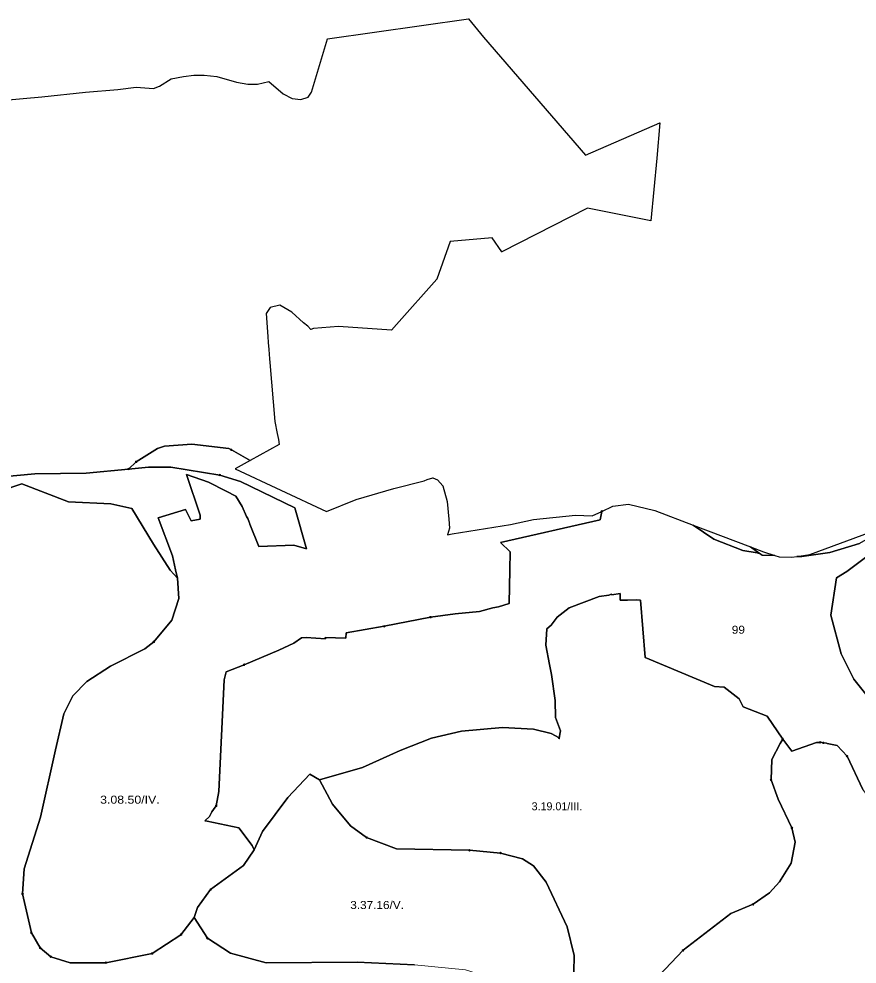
# Model space of a CAD drawing. Extents: x -650455 to -642254, y -1075222 to -1066610.
# Drawn here: x -644814 to -643766, y -1069625 to -1068444 of the extents above; entities that cross this region are included whole.
import ezdxf
from ezdxf.enums import TextEntityAlignment as Align

# ---------------------------------------------------------------- set-up
doc = ezdxf.new("R2010")
doc.units = 0
doc.header["$LTSCALE"] = 4
doc.header["$PDMODE"] = 32
doc.header["$PDSIZE"] = 2
for name, color, linetype, lineweight in [('1', 7, 'Continuous', 25), ('11', 7, 'Continuous', 13), ('13', 7, 'Continuous', 13), ('14', 7, 'Continuous', 13), ('15', 7, 'Continuous', 13)]:
    doc.layers.add(name, color=color, linetype=linetype, lineweight=lineweight)
doc.layers.add('2', color=7, linetype='Continuous')

msp = doc.modelspace()

# ---------------------------------------------------------------- linework, layer by layer
at = {"layer": '1'}
for points in [[(-644865.029, -1068548.219), (-644785.549, -1068541.387), (-644730.78, -1068535.476), (-644690.424, -1068532.018), (-644667.364, -1068529.135), (-644646.033, -1068530.865), (-644638.25, -1068527.839), (-644623.837, -1068518.903), (-644608.271, -1068515.731), (-644595.299, -1068514.291), (-644582.328, -1068514.291), (-644566.762, -1068515.875), (-644542.26, -1068523.081), (-644527.847, -1068525.533), (-644515.877, -1068525.233), (-644501.596, -1068522.127), (-644483.899, -1068537.657), (-644472.722, -1068543.249), (-644461.856, -1068544.49), (-644452.542, -1068541.695), (-644448.506, -1068535.484), (-644428.326, -1068468.706), (-644252.29, -1068443.858), (-644233.352, -1068466.531)], [(-644233.352, -1068466.531), (-644105.749, -1068614.065), (-644012.919, -1068573.686), (-644016.645, -1068617.791), (-644024.406, -1068696.372), (-644103.575, -1068680.531), (-644210.376, -1068734.886), (-644222.484, -1068717.492), (-644275.263, -1068722.151), (-644291.718, -1068769.051), (-644342.212, -1068825.639), (-644348.534, -1068832.723), (-644414.741, -1068828.435), (-644445.788, -1068830.92), (-644449.35, -1068832.01), (-644452.802, -1068828.111), (-644458.176, -1068823.819), (-644472.804, -1068810.471), (-644488.017, -1068801.775), (-644500.125, -1068804.57), (-644505.092, -1068812.026), (-644502.911, -1068840.68), (-644502.338, -1068848.206), (-644501.654, -1068857.202), (-644500.772, -1068868.778), (-644500.435, -1068873.213), (-644494.115, -1068947.011), (-644491.207, -1068961.854), (-644489.705, -1068969.518), (-644488.773, -1068975.73), (-644525.181, -1068995.897), (-644548.5, -1068982.501), (-644551.5, -1068981.001), (-644598, -1068975.5), (-644632, -1068978.001), (-644641, -1068981.001), (-644667.5, -1068997.501), (-644677, -1069006.501), (-644730, -1069011.5), (-644794, -1069012.5)], [(-644640, -1069067.501), (-644606, -1069057), (-644598.81, -1069071.02), (-644587.5, -1069069), (-644587.5, -1069064), (-644604.5, -1069013.501), (-644577, -1069023.001), (-644555, -1069034.001), (-644543, -1069040.5), (-644535.13, -1069053.181), (-644529.464, -1069065.769), (-644528, -1069068.5), (-644526.232, -1069072.948), (-644525.83, -1069073.84), (-644525.345, -1069075.177), (-644514.093, -1069103.478), (-644470.37, -1069101.551), (-644454.63, -1069106.281), (-644469.28, -1069054.8), (-644537, -1069022.001), (-644563, -1069014.001), (-644624, -1069004), (-644652, -1069004), (-644677, -1069006.501), (-644667.5, -1068997.501), (-644641, -1068981.001), (-644632, -1068978.001), (-644598, -1068975.5), (-644551.5, -1068981.001), (-644548.5, -1068982.501), (-644525.181, -1068995.897)], [(-644839.5, -1069016.5), (-644794, -1069012.5), (-644730, -1069011.5), (-644677, -1069006.501), (-644652, -1069004), (-644624, -1069004), (-644563, -1069014.001), (-644537, -1069022.001), (-644469.28, -1069054.8), (-644454.63, -1069106.281), (-644470.37, -1069101.551), (-644514.093, -1069103.478), (-644525.345, -1069075.177), (-644525.83, -1069073.84), (-644526.232, -1069072.948), (-644528, -1069068.5), (-644529.464, -1069065.769), (-644535.13, -1069053.181), (-644543, -1069040.5)], [(-644525.181, -1068995.897), (-644543.726, -1069006.168), (-644429.474, -1069059.592), (-644392.528, -1069044.683), (-644345.647, -1069030.706), (-644307.77, -1069021.078), (-644303.667, -1069019.725), (-644296.6, -1069017.395), (-644290.701, -1069019.88), (-644284.181, -1069027.644), (-644278.903, -1069047.211), (-644276.818, -1069069.004), (-644275.887, -1069080.185), (-644278.515, -1069088.547), (-644272.734, -1069087.604), (-644199.819, -1069075.69), (-644170.945, -1069069.479), (-644118.477, -1069064.198), (-644097.468, -1069064.949), (-644085.664, -1069059.379), (-644087.5, -1069070.001), (-644212, -1069098.501), (-644200, -1069110), (-644200.5, -1069132.5), (-644201.5, -1069174.5), (-644214.53, -1069178.601), (-644221.69, -1069179.9), (-644238.23, -1069184.641), (-644268.7, -1069187.421), (-644299.717, -1069191.596), (-644357.5, -1069203), (-644405, -1069211), (-644405.5, -1069218), (-644431.362, -1069216.923), (-644430.91, -1069218.821), (-644454.87, -1069217.05), (-644460.97, -1069217.61), (-644470.64, -1069224.001), (-644489.27, -1069233.04), (-644532.71, -1069251.121)], [(-644794, -1069012.5), (-644839.5, -1069016.5)], [(-644543, -1069040.5), (-644555, -1069034.001), (-644577, -1069023.001), (-644604.5, -1069013.501), (-644587.5, -1069064), (-644587.5, -1069069), (-644598.81, -1069071.02), (-644606, -1069057), (-644640, -1069067.501), (-644622, -1069115.001), (-644618.28, -1069132.421), (-644616, -1069143.001)], [(-644616, -1069143.001), (-644625, -1069133), (-644646, -1069100.5), (-644673, -1069056), (-644699, -1069050.001), (-644752, -1069047.5), (-644810.5, -1069025), (-644836.38, -1069033.691)], [(-644836.38, -1069033.691), (-644810.5, -1069025), (-644752, -1069047.5), (-644699, -1069050.001)], [(-644699, -1069050.001), (-644673, -1069056), (-644646, -1069100.5), (-644625, -1069133), (-644616, -1069143.001)], [(-644357.5, -1069203), (-644299.717, -1069191.596), (-644268.7, -1069187.421), (-644238.23, -1069184.641), (-644221.69, -1069179.9), (-644214.53, -1069178.601), (-644201.5, -1069174.5), (-644200.5, -1069132.5), (-644200, -1069110), (-644212, -1069098.501), (-644087.5, -1069070.001), (-644085.664, -1069059.379), (-644071.881, -1069052.874), (-644052.196, -1069050.206), (-644019.287, -1069058.281), (-643971.567, -1069076.484)], [(-644532.71, -1069251.121), (-644555, -1069260), (-644557.5, -1069270.001), (-644564, -1069409.5), (-644567.5, -1069427.501), (-644571, -1069432.001), (-644572.97, -1069435.121), (-644575.93, -1069440.66), (-644581.87, -1069446.281), (-644578.92, -1069446.801), (-644539, -1069454.881), (-644522.5, -1069477), (-644520, -1069482.5), (-644533.5, -1069502), (-644574.5, -1069532.001), (-644591, -1069554.5), (-644595, -1069567), (-644611.5, -1069588.501), (-644647.5, -1069612), (-644705.5, -1069623.5), (-644750, -1069623.5), (-644774, -1069616), (-644787.5, -1069605.001), (-644798.5, -1069586), (-644809.5, -1069537.5), (-644807.5, -1069506), (-644787, -1069441.5), (-644768.5, -1069357.501), (-644758, -1069312.5), (-644746.5, -1069290.001), (-644729, -1069272), (-644699.5, -1069253.001), (-644656.5, -1069231), (-644645.5, -1069222.5), (-644623, -1069195.501), (-644614, -1069168.501), (-644616, -1069143.001), (-644618.28, -1069132.421), (-644622, -1069115.001), (-644640, -1069067.501)], [(-643971.567, -1069076.484), (-643945.5, -1069094), (-643909.5, -1069108.5), (-643891.564, -1069111.125), (-643891.55, -1069111.13), (-643890.13, -1069111.65), (-643888.83, -1069111.611), (-643888.824, -1069111.61), (-643885, -1069114), (-643869.425, -1069114.63), (-643864.053, -1069116.363), (-643848.219, -1069116.674), (-643842.005, -1069115.738), (-643835.5, -1069116.001), (-643800.5, -1069111.001), (-643763.5, -1069099.501)], [(-643747.75, -1069110.71), (-643779.31, -1069134.631), (-643792.04, -1069142.271), (-643799.5, -1069189.001), (-643786.5, -1069237.501), (-643770.5, -1069269.001), (-643744, -1069302.5)], [(-643744, -1069302.5), (-643770.5, -1069269.001), (-643786.5, -1069237.501), (-643799.5, -1069189.001), (-643792.04, -1069142.271), (-643779.31, -1069134.631), (-643747.75, -1069110.71)], [(-644616, -1069143.001), (-644614, -1069168.501), (-644623, -1069195.501), (-644645.5, -1069222.5), (-644656.5, -1069231), (-644699.5, -1069253.001), (-644729, -1069272), (-644746.5, -1069290.001), (-644758, -1069312.5), (-644768.5, -1069357.501), (-644787, -1069441.5), (-644807.5, -1069506), (-644809.5, -1069537.5), (-644798.5, -1069586), (-644787.5, -1069605.001), (-644774, -1069616), (-644750, -1069623.5), (-644705.5, -1069623.5), (-644647.5, -1069612), (-644611.5, -1069588.501), (-644595, -1069567), (-644578.5, -1069593.001), (-644549.5, -1069611.5), (-644505, -1069623.5), (-644391.5, -1069623), (-644319.5, -1069626.001)], [(-644209.5, -1069329.501), (-644171, -1069331.5), (-644149, -1069337.001), (-644139, -1069342.501), (-644137, -1069333.501), (-644143.54, -1069317.051), (-644144.05, -1069295.67), (-644148.22, -1069263.22), (-644151.11, -1069250.7), (-644155.37, -1069226.72), (-644154.36, -1069206.06), (-644148.931, -1069201.554), (-644141.5, -1069191.501), (-644126.5, -1069180.001), (-644089, -1069166), (-644076.643, -1069164.135), (-644073.35, -1069162.84), (-644073.229, -1069163.62), (-644062.5, -1069162), (-644062.5, -1069170.5), (-644053.451, -1069170.5), (-644042.37, -1069169.77), (-644037, -1069170.5), (-644031.5, -1069242), (-643944.89, -1069278.321), (-643932.5, -1069279), (-643914, -1069293.501), (-643909, -1069303.5), (-643879, -1069315.5), (-643859.5, -1069344)], [(-643759.5, -1069407.001), (-643779, -1069365.501), (-643791.5, -1069352), (-643803.851, -1069349.648), (-643804.83, -1069348.991), (-643808.723, -1069348.72), (-643812.5, -1069348), (-643813.705, -1069348.374), (-643817.06, -1069348.14), (-643848, -1069359.001), (-643859.5, -1069344), (-643879, -1069315.5), (-643909, -1069303.5), (-643914, -1069293.501), (-643932.5, -1069279), (-643944.89, -1069278.321), (-644031.5, -1069242), (-644037, -1069170.5), (-644042.37, -1069169.77), (-644053.451, -1069170.5), (-644062.5, -1069170.5), (-644062.5, -1069162), (-644073.229, -1069163.62), (-644073.35, -1069162.84), (-644076.643, -1069164.135), (-644089, -1069166), (-644126.5, -1069180.001), (-644141.5, -1069191.501), (-644148.931, -1069201.554), (-644154.36, -1069206.06), (-644155.37, -1069226.72), (-644151.11, -1069250.7)], [(-644151.11, -1069250.7), (-644148.22, -1069263.22), (-644144.05, -1069295.67), (-644143.54, -1069317.051), (-644137, -1069333.501), (-644139, -1069342.501), (-644149, -1069337.001), (-644171, -1069331.5), (-644209.5, -1069329.501), (-644261, -1069334.001), (-644298.5, -1069343), (-644337.6, -1069358.4), (-644350.5, -1069364), (-644384.5, -1069379.5), (-644438.5, -1069395.001), (-644450.5, -1069388), (-644478, -1069417), (-644509.5, -1069459.501), (-644520, -1069482.5), (-644522.5, -1069477), (-644539, -1069454.881), (-644578.92, -1069446.801), (-644581.87, -1069446.281), (-644575.93, -1069440.66), (-644572.97, -1069435.121), (-644571, -1069432.001), (-644567.5, -1069427.501), (-644564, -1069409.5), (-644557.5, -1069270.001), (-644555, -1069260), (-644532.71, -1069251.121), (-644489.27, -1069233.04), (-644470.64, -1069224.001), (-644460.97, -1069217.61), (-644454.87, -1069217.05), (-644430.91, -1069218.821), (-644431.362, -1069216.923), (-644405.5, -1069218), (-644405, -1069211), (-644357.5, -1069203)], [(-644121, -1069656), (-644120, -1069614.5), (-644129, -1069578.5), (-644155, -1069523), (-644171, -1069502.5), (-644184.5, -1069493.5), (-644212, -1069486.5), (-644251, -1069483.001), (-644342, -1069481), (-644379.5, -1069467.001), (-644399.5, -1069452.5), (-644422, -1069425.5), (-644438.5, -1069395.001), (-644384.5, -1069379.5), (-644350.5, -1069364), (-644337.6, -1069358.4), (-644298.5, -1069343), (-644261, -1069334.001), (-644209.5, -1069329.501)], [(-644014, -1069639.5), (-643984, -1069608), (-643924.5, -1069562), (-643896.5, -1069550.5), (-643876, -1069536.001), (-643863.5, -1069522.5), (-643849, -1069499.001), (-643844, -1069473), (-643848, -1069455.001), (-643865, -1069419.001), (-643874, -1069395.001), (-643873, -1069369.501), (-643862.5, -1069349.501), (-643859.5, -1069344), (-643848, -1069359.001), (-643817.06, -1069348.14)], [(-643859.5, -1069344), (-643862.5, -1069349.501), (-643873, -1069369.501), (-643874, -1069395.001), (-643865, -1069419.001), (-643848, -1069455.001), (-643844, -1069473), (-643849, -1069499.001), (-643863.5, -1069522.5), (-643876, -1069536.001), (-643896.5, -1069550.5), (-643924.5, -1069562), (-643984, -1069608), (-644014, -1069639.5)], [(-643817.06, -1069348.14), (-643813.705, -1069348.374), (-643812.5, -1069348), (-643808.723, -1069348.72), (-643804.83, -1069348.991), (-643803.851, -1069349.648), (-643791.5, -1069352), (-643779, -1069365.501), (-643759.5, -1069407.001)], [(-644319.5, -1069626.001), (-644391.5, -1069623), (-644505, -1069623.5), (-644549.5, -1069611.5), (-644578.5, -1069593.001), (-644595, -1069567), (-644591, -1069554.5), (-644574.5, -1069532.001), (-644533.5, -1069502), (-644520, -1069482.5), (-644509.5, -1069459.501), (-644478, -1069417), (-644450.5, -1069388), (-644438.5, -1069395.001), (-644422, -1069425.5), (-644399.5, -1069452.5), (-644379.5, -1069467.001), (-644342, -1069481), (-644251, -1069483.001), (-644212, -1069486.5), (-644184.5, -1069493.5), (-644171, -1069502.5), (-644155, -1069523), (-644129, -1069578.5), (-644120, -1069614.5), (-644121, -1069656)]]:
    msp.add_lwpolyline(points, dxfattribs=at)
for points in [[(-643888.83, -1069111.611), (-643890.13, -1069111.65), (-643891.55, -1069111.13), (-643891.564, -1069111.125), (-643909.5, -1069108.5), (-643945.5, -1069094), (-643971.567, -1069076.484), (-643899.857, -1069103.837), (-643889, -1069111.501), (-643888.836, -1069111.606)], [(-643800.5, -1069111.001), (-643835.5, -1069116.001), (-643842.005, -1069115.738), (-643825.555, -1069113.258), (-643740.798, -1069082.197), (-643738.043, -1069084.954), (-643763.5, -1069099.501)], [(-643883.302, -1069110.152), (-643869.425, -1069114.63), (-643885, -1069114), (-643888.824, -1069111.61), (-643888.83, -1069111.611), (-643888.836, -1069111.606), (-643889, -1069111.501), (-643899.857, -1069103.837)]]:
    msp.add_lwpolyline(points, close=True, dxfattribs=at)
at = {"layer": '11'}
msp.add_line((-643808.723, -1069348.72), (-643812.5, -1069348), dxfattribs=at)
for points in [[(-644667.5, -1068997.501), (-644641, -1068981.001), (-644632, -1068978.001), (-644598, -1068975.5), (-644551.5, -1068981.001), (-644548.5, -1068982.501), (-644525.181, -1068995.897), (-644488.773, -1068975.73), (-644489.705, -1068969.518), (-644491.207, -1068961.854), (-644494.115, -1068947.011), (-644500.435, -1068873.213), (-644500.772, -1068868.778), (-644501.654, -1068857.202), (-644502.338, -1068848.206), (-644502.911, -1068840.68), (-644505.092, -1068812.026), (-644500.125, -1068804.57), (-644488.017, -1068801.775), (-644472.804, -1068810.471), (-644458.176, -1068823.819), (-644452.802, -1068828.111), (-644449.35, -1068832.01), (-644445.788, -1068830.92), (-644414.741, -1068828.435), (-644348.534, -1068832.723), (-644342.212, -1068825.639), (-644291.718, -1068769.051), (-644275.263, -1068722.151), (-644222.484, -1068717.492), (-644210.376, -1068734.886), (-644103.575, -1068680.531), (-644024.406, -1068696.372), (-644016.645, -1068617.791), (-644012.919, -1068573.686), (-644105.749, -1068614.065), (-644233.352, -1068466.531), (-644252.29, -1068443.858), (-644428.326, -1068468.706), (-644448.506, -1068535.484)], [(-644448.506, -1068535.484), (-644452.542, -1068541.695), (-644461.856, -1068544.49), (-644472.722, -1068543.249), (-644483.899, -1068537.657), (-644501.596, -1068522.127), (-644515.877, -1068525.233), (-644527.847, -1068525.533), (-644542.26, -1068523.081), (-644566.762, -1068515.875), (-644582.328, -1068514.291), (-644595.299, -1068514.291), (-644608.271, -1068515.731), (-644623.837, -1068518.903), (-644638.25, -1068527.839), (-644646.033, -1068530.865), (-644667.364, -1068529.135), (-644690.424, -1068532.018), (-644730.78, -1068535.476), (-644785.549, -1068541.387), (-644865.029, -1068548.219)], [(-644884.5, -1069007), (-644872.563, -1069007.374), (-644875.563, -1068993.501), (-644867.701, -1068989.497), (-644855.56, -1068983.38), (-644851.16, -1069004.211), (-644851.147, -1069004.26), (-644850.813, -1069004.126), (-644849.51, -1069009.955), (-644839.5, -1069016.5), (-644794, -1069012.5), (-644730, -1069011.5), (-644677, -1069006.501), (-644667.5, -1068997.501)], [(-644809.5, -1069537.5), (-644807.5, -1069506), (-644787, -1069441.5), (-644768.5, -1069357.501), (-644758, -1069312.5), (-644746.5, -1069290.001), (-644729, -1069272), (-644699.5, -1069253.001), (-644656.5, -1069231), (-644645.5, -1069222.5), (-644623, -1069195.501), (-644614, -1069168.501), (-644616, -1069143.001), (-644625, -1069133), (-644646, -1069100.5), (-644673, -1069056), (-644699, -1069050.001), (-644752, -1069047.5), (-644810.5, -1069025), (-644836.38, -1069033.691)], [(-643859.5, -1069344), (-643862.5, -1069349.501), (-643873, -1069369.501), (-643874, -1069395.001)], [(-643812.5, -1069348), (-643813.705, -1069348.374), (-643817.06, -1069348.14), (-643848, -1069359.001), (-643859.5, -1069344)], [(-643779, -1069365.501), (-643791.5, -1069352), (-643803.851, -1069349.648), (-643804.83, -1069348.991), (-643808.723, -1069348.72)], [(-643727.662, -1069449.608), (-643759.5, -1069407.001), (-643779, -1069365.501)], [(-643874, -1069395.001), (-643865, -1069419.001), (-643848, -1069455.001), (-643844, -1069473), (-643849, -1069499.001), (-643863.5, -1069522.5), (-643876, -1069536.001), (-643896.5, -1069550.5), (-643924.5, -1069562), (-643984, -1069608)], [(-644787.5, -1069605.001), (-644798.5, -1069586), (-644809.5, -1069537.5)], [(-644578.5, -1069593.001), (-644595, -1069567), (-644611.5, -1069588.501)], [(-644611.5, -1069588.501), (-644647.5, -1069612), (-644705.5, -1069623.5)], [(-644217.5, -1069644.5), (-644256, -1069632.5), (-644319.5, -1069626.001), (-644391.5, -1069623), (-644505, -1069623.5), (-644549.5, -1069611.5), (-644578.5, -1069593.001)], [(-644705.5, -1069623.5), (-644750, -1069623.5), (-644774, -1069616), (-644787.5, -1069605.001)], [(-643984, -1069608), (-644014, -1069639.5), (-644062, -1069701), (-644056, -1069698.501), (-644086, -1069751.501), (-644087.496, -1069755.989), (-643999.727, -1069751.999), (-643995.5, -1069739.501)]]:
    msp.add_lwpolyline(points, dxfattribs=at)
for p in [(-644667.5, -1068997.501), (-643859.5, -1069344), (-643812.5, -1069348), (-643808.723, -1069348.72), (-643779, -1069365.501), (-643874, -1069395.001), (-644809.5, -1069537.5), (-644611.5, -1069588.501), (-644578.5, -1069593.001), (-644787.5, -1069605.001), (-643984, -1069608), (-644705.5, -1069623.5)]:
    msp.add_point(p, dxfattribs=at)
at = {"layer": '13'}
msp.add_line((-644251, -1069483.001), (-644212, -1069486.5), dxfattribs=at)
for points in [[(-643848, -1069455.001), (-643865, -1069419.001), (-643874, -1069395.001), (-643873, -1069369.501), (-643862.5, -1069349.501), (-643859.5, -1069344), (-643879, -1069315.5), (-643909, -1069303.5), (-643914, -1069293.501), (-643932.5, -1069279), (-643944.89, -1069278.321), (-644031.5, -1069242), (-644037, -1069170.5), (-644042.37, -1069169.77), (-644053.451, -1069170.5), (-644062.5, -1069170.5), (-644062.5, -1069162), (-644073.229, -1069163.62), (-644073.35, -1069162.84), (-644076.643, -1069164.135), (-644089, -1069166), (-644126.5, -1069180.001), (-644141.5, -1069191.501), (-644148.931, -1069201.554), (-644154.36, -1069206.06), (-644155.37, -1069226.72), (-644151.11, -1069250.7), (-644148.22, -1069263.22), (-644144.05, -1069295.67), (-644143.54, -1069317.051), (-644137, -1069333.501), (-644139, -1069342.501)], [(-644139, -1069342.501), (-644149, -1069337.001), (-644171, -1069331.5), (-644209.5, -1069329.501), (-644261, -1069334.001), (-644298.5, -1069343), (-644337.6, -1069358.4), (-644350.5, -1069364), (-644384.5, -1069379.5), (-644438.5, -1069395.001), (-644422, -1069425.5), (-644399.5, -1069452.5), (-644379.5, -1069467.001)], [(-643896.5, -1069550.5), (-643876, -1069536.001), (-643863.5, -1069522.5), (-643849, -1069499.001), (-643844, -1069473), (-643848, -1069455.001)], [(-644379.5, -1069467.001), (-644342, -1069481), (-644251, -1069483.001)], [(-644212, -1069486.5), (-644184.5, -1069493.5), (-644171, -1069502.5), (-644155, -1069523), (-644129, -1069578.5), (-644120, -1069614.5), (-644121, -1069656), (-644126, -1069675.5), (-644140, -1069691.001), (-644156, -1069689), (-644140, -1069712), (-644126, -1069716.5), (-644097.5, -1069715.001), (-644062, -1069701), (-644014, -1069639.5), (-643984, -1069608)], [(-643984, -1069608), (-643924.5, -1069562), (-643896.5, -1069550.5)]]:
    msp.add_lwpolyline(points, dxfattribs=at)
for p in [(-644139, -1069342.501), (-643848, -1069455.001), (-644379.5, -1069467.001), (-644251, -1069483.001), (-644212, -1069486.5), (-643896.5, -1069550.5), (-643984, -1069608)]:
    msp.add_point(p, dxfattribs=at)
at = {"layer": '14'}
for p, q in [((-644357.5, -1069203), (-644299.717, -1069191.596)), ((-644798.5, -1069586), (-644787.5, -1069605.001)), ((-644787.5, -1069605.001), (-644774, -1069616))]:
    msp.add_line(p, q, dxfattribs=at)
for points in [[(-644548.5, -1068982.501), (-644551.5, -1068981.001), (-644598, -1068975.5), (-644632, -1068978.001), (-644641, -1068981.001), (-644667.5, -1068997.501), (-644677, -1069006.501)], [(-644085.664, -1069059.379), (-644097.468, -1069064.949), (-644118.477, -1069064.198), (-644170.945, -1069069.479), (-644199.819, -1069075.69), (-644272.734, -1069087.604), (-644278.515, -1069088.547), (-644275.887, -1069080.185), (-644276.818, -1069069.004), (-644278.903, -1069047.211), (-644284.181, -1069027.644), (-644290.701, -1069019.88), (-644296.6, -1069017.395), (-644303.667, -1069019.725), (-644307.77, -1069021.078), (-644345.647, -1069030.706), (-644392.528, -1069044.683), (-644429.474, -1069059.592), (-644543.726, -1069006.168), (-644525.181, -1068995.897), (-644548.5, -1068982.501)], [(-644677, -1069006.501), (-644652, -1069004), (-644624, -1069004), (-644563, -1069014.001)], [(-644563, -1069014.001), (-644537, -1069022.001), (-644469.28, -1069054.8), (-644454.63, -1069106.281), (-644470.37, -1069101.551), (-644514.093, -1069103.478), (-644525.345, -1069075.177), (-644525.83, -1069073.84), (-644526.232, -1069072.948), (-644528, -1069068.5), (-644529.464, -1069065.769), (-644535.13, -1069053.181), (-644543, -1069040.5), (-644555, -1069034.001), (-644577, -1069023.001), (-644604.5, -1069013.501), (-644587.5, -1069064), (-644587.5, -1069069), (-644598.81, -1069071.02), (-644606, -1069057), (-644640, -1069067.501), (-644622, -1069115.001), (-644618.28, -1069132.421), (-644616, -1069143.001), (-644614, -1069168.501), (-644623, -1069195.501), (-644645.5, -1069222.5)], [(-644299.717, -1069191.596), (-644268.7, -1069187.421), (-644238.23, -1069184.641), (-644221.69, -1069179.9), (-644214.53, -1069178.601), (-644201.5, -1069174.5), (-644200.5, -1069132.5), (-644200, -1069110), (-644212, -1069098.501), (-644087.5, -1069070.001), (-644085.664, -1069059.379)], [(-643727.5, -1069127.001), (-643733.5, -1069107.501), (-643739.66, -1069104.58), (-643747.75, -1069110.71), (-643779.31, -1069134.631), (-643792.04, -1069142.271), (-643799.5, -1069189.001), (-643786.5, -1069237.501), (-643770.5, -1069269.001), (-643744, -1069302.5)], [(-644532.71, -1069251.121), (-644489.27, -1069233.04), (-644470.64, -1069224.001), (-644460.97, -1069217.61), (-644454.87, -1069217.05), (-644430.91, -1069218.821), (-644431.362, -1069216.923), (-644405.5, -1069218), (-644405, -1069211), (-644357.5, -1069203)], [(-644645.5, -1069222.5), (-644656.5, -1069231), (-644699.5, -1069253.001), (-644729, -1069272), (-644746.5, -1069290.001), (-644758, -1069312.5), (-644768.5, -1069357.501), (-644787, -1069441.5), (-644807.5, -1069506), (-644809.5, -1069537.5), (-644798.5, -1069586)], [(-644567.5, -1069427.501), (-644564, -1069409.5), (-644557.5, -1069270.001), (-644555, -1069260), (-644532.71, -1069251.121)], [(-644574.5, -1069532.001), (-644533.5, -1069502), (-644520, -1069482.5), (-644522.5, -1069477), (-644539, -1069454.881), (-644578.92, -1069446.801), (-644581.87, -1069446.281), (-644575.93, -1069440.66), (-644572.97, -1069435.121), (-644571, -1069432.001), (-644567.5, -1069427.501)], [(-644647.5, -1069612), (-644611.5, -1069588.501), (-644595, -1069567), (-644591, -1069554.5), (-644574.5, -1069532.001)], [(-644774, -1069616), (-644750, -1069623.5), (-644705.5, -1069623.5), (-644647.5, -1069612)]]:
    msp.add_lwpolyline(points, dxfattribs=at)
for p in [(-644548.5, -1068982.501), (-644677, -1069006.501), (-644563, -1069014.001), (-644085.664, -1069059.379), (-644299.717, -1069191.596), (-644357.5, -1069203), (-644645.5, -1069222.5), (-644532.71, -1069251.121), (-644567.5, -1069427.501), (-644574.5, -1069532.001), (-644798.5, -1069586), (-644787.5, -1069605.001), (-644774, -1069616), (-644647.5, -1069612)]:
    msp.add_point(p, dxfattribs=at)
at = {"layer": '15'}
msp.add_lwpolyline([(-644121, -1069656), (-644120, -1069614.5), (-644129, -1069578.5), (-644155, -1069523), (-644171, -1069502.5), (-644184.5, -1069493.5), (-644212, -1069486.5), (-644251, -1069483.001), (-644342, -1069481), (-644379.5, -1069467.001), (-644399.5, -1069452.5), (-644422, -1069425.5), (-644438.5, -1069395.001), (-644450.5, -1069388), (-644478, -1069417), (-644509.5, -1069459.501), (-644520, -1069482.5), (-644533.5, -1069502), (-644574.5, -1069532.001), (-644591, -1069554.5), (-644595, -1069567), (-644578.5, -1069593.001), (-644549.5, -1069611.5), (-644505, -1069623.5), (-644391.5, -1069623), (-644319.5, -1069626.001)], dxfattribs=at)

# ---------------------------------------------------------------- texts
at = {"layer": '2'}
for s, width, p in [('99', 1.1, (-643914.889, -1069212.32)), ('3.08.50/IV.', 1.15, (-644675.312, -1069424.737)), ('3.37.16/V.', 1.1, (-644366.39, -1069556.37))]:
    msp.add_text(s, height=10, dxfattribs=dict(at, width=width)).set_placement(p, align=Align.CENTER)
msp.add_text('3.19.01/III.', height=10, dxfattribs=at).set_placement((-644141.691, -1069433.015), align=Align.CENTER)

doc.saveas('drawing.dxf')
